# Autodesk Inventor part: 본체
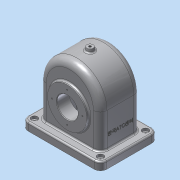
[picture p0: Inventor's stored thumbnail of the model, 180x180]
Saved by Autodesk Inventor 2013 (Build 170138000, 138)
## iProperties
Created: 2016-10
Part Number: 본체
Material: 알루미늄 6061
Document SubType Name: Modeling
Designer: Administrator
Mass: 1165.05 g
Surface Area: 1200.05 cm^2
Volume: 429.908 cm^3
Density: 2.71 g/cm^3
Author: Administrator
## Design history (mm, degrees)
sketch "스케치1"
  geometry: L1 (-43, 75)-(43, 75); L2 (55, 63)-(55, -63); L3 (43, -75)-(-43, -75); L4 (-55, -63)-(-55, 63); A1 r 12 centre (-43, 63) between (-43, 75) and (-55, 63); A2 r 12 centre (43, 63) between (55, 63) and (43, 75); A3 r 12 centre (43, -63) between (43, -75) and (55, -63); A4 r 12 centre (-43, -63) between (-55, -63) and (-43, -75); 6 further points
  constraints: 8 end point, 8 point on circle, 8 tangent, 6 point on line, 4 centre point, 3 equal radius, 2 midpoint, 2 parallel, 1 horizontal, 1 horizontal alignment, 1 perpendicular, 1 vertical alignment
  dimensions: "d0" = 110 distance of point (-55, 75) point (55, 75); "d2" = 150 distance of point (55, 75) point (55, -75); "d3" = 12 radius of A1
extrude "돌출1" new body sketch "스케치1" distance "d4" = 15; taper "d5" = 0 deg
sketch "스케치2"
  geometry: L1 (63, 15)-(-63, 15) reference; L2 (-63, 15)-(-75, 15) reference; L3 (75, 15)-(63, 15) reference; L4 (-58, 15)-(-58, 80); L5 (58, 80)-(58, 15); A1 r 58 centre (0, 80) between (58, 80) and (-58, 80); 1 further point
  constraints: 4 end point, 2 perpendicular, 2 point on circle, 2 point on line, 2 tangent, 1 centre point, 1 vertical alignment
  dimensions: "d6" = 80 distance of point (0, 0) A1.centre; "d7" = 58 radius of A1
extrude "돌출2" join sketch "스케치2" stored distance "d8" = 77; taper "d9" = 0 deg
sketch "스케치3"
  geometry: L1 (58, 80)-(58, 15) reference; L2 (-58, 15)-(-58, 80) reference; L3 (-63, 0)-(63, 0) reference; L4 (-52, 0)-(-52, 80); L5 (52, 80)-(52, 0); A1 r 58 centre (0, 80) between (58, 80) and (-58, 80) reference; A2 r 52 centre (0, 80) between (52, 80) and (-52, 80); 1 further point
  constraints: 4 end point, 2 point on circle, 2 point on line, 1 centre point
  dimensions: "d10" = 6 distance between parallel lines of L1 L5; "d11" = 6 distance between parallel lines of L2 L4; "d12" = 6 radial gap between concentric circles of A1 A2
extrude "돌출3" cut sketch "스케치3" stored distance "d13" = 67; taper "d14" = 0 deg
sketch "스케치4"
  geometry: L1 (0, 63)-(0, -63) reference; C1 r 31 at (-65, 0); 2 further points
  constraints: 1 centre point, 1 horizontal alignment, 1 midpoint
  dimensions: "d15" = 62 diameter of C1; "d17" = 65 distance from line of L1 C1.centre
extrude "돌출4" join sketch "스케치4" distance "d18" = 10; taper "d19" = 0 deg
sketch "스케치5"
  geometry: C1 r 37.5 at (65, 0); 1 further point
  constraints: 1 centre point, 1 horizontal alignment
  dimensions: "d20" = 75 diameter of C1; "d22" = 65 distance of C1.centre point (0, 0)
extrude "돌출5" join sketch "스케치5" distance "d23" = 5; taper "d24" = 0 deg
node "작업 평면1"
sketch "스케치6"
  geometry: C1 r 6 at (0, 0); 1 further point
  constraints: 1 centre point, 1 coincident
  dimensions: "d26" = 12 diameter of C1
extrude "돌출6" join sketch "스케치6" distance "d28" = 10; taper "d29" = 10 deg
sketch "스케치7"
  geometry: L1 (43.5, 27.5)-(43.5, 102.5) reference; L2 (33.5, 80)-(33.5, 132) reference; L3 (33.5, 0)-(33.5, 80) reference; L4 (43.5, 65)-(19.5, 65); L5 (19.5, 65)-(19.5, 93); L6 (19.5, 93)-(33.5, 104.747); L7 (33.5, 104.747)-(33.5, 65); 1 further point
  constraints: 8 end point, 3 point on line, 2 perpendicular, 1 midpoint
  dimensions: "d30" = 56 diameter of L5.end L4; "d32" = 50 deg angle of L6 L5; "d34" = 24 distance between parallel lines of L5 L1
revolve "회전1" sketch "스케치7" stored, may be unused: angle "d35" = 90 deg
hole "구멍1" diameter "d38" = 40; stored, may be unused: countersink angle "d42" = 90 deg, drill point angle "d44" = 118 deg; dims "d36" = 10, "d37" = 10, "d39" = 6, "d40" = 4, "d41" = 2, "d43" = 8
hole "구멍2" diameter "d47" = 4.459; stored, may be unused: countersink angle "d51" = 90 deg, drill point angle "d53" = 118 deg; dims "d48" = 20, "d49" = 4, "d50" = 2, "d52" = 8, "d124" = 10, "d125" = 10
hole "구멍3" diameter "d56" = 5; stored, may be unused: countersink angle "d60" = 90 deg, drill point angle "d62" = 118 deg; dims "d54" = 10, "d55" = 10, "d57" = 6, "d58" = 12, "d59" = 5, "d61" = 8
hole "구멍4" diameter "d65" = 5; stored, may be unused: countersink angle "d69" = 90 deg, drill point angle "d71" = 118 deg; dims "d63" = 10, "d64" = 10, "d66" = 6, "d67" = 12, "d68" = 5, "d70" = 8
hole "구멍5" diameter "d74" = 5; stored, may be unused: countersink angle "d78" = 90 deg, drill point angle "d80" = 118 deg; dims "d72" = 10, "d73" = 10, "d75" = 6, "d76" = 12, "d77" = 5, "d79" = 8
hole "구멍6" diameter "d83" = 5; stored, may be unused: countersink angle "d87" = 90 deg, drill point angle "d89" = 118 deg; dims "d81" = 10, "d82" = 10, "d84" = 6, "d85" = 12, "d86" = 5, "d88" = 8
sketch "스케치8"
  geometry: C1 r 20 at (0, 0) reference; 2 further points
  constraints: 1 horizontal alignment
  dimensions: "d90" = 26 distance of point (26, 0) C1.centre
hole "구멍7" sketch "스케치8" at (26, 0) diameter "d91" = 2.459; stored, may be unused: countersink angle "d95" = 90 deg, drill point angle "d97" = 118 deg; dims "d92" = 6, "d93" = 12, "d94" = 5, "d96" = 8
sketch "스케치9"
  geometry: C1 r 20 at (0, 0) reference; 2 further points
  constraints: 1 horizontal alignment
  dimensions: "d101" = 29 distance of C1.centre point (-29, 0)
hole "구멍8" sketch "스케치9" at (-29, 0) diameter "d102" = 2.459; stored, may be unused: countersink angle "d106" = 90 deg, drill point angle "d108" = 118 deg; dims "d103" = 6, "d104" = 12, "d105" = 5, "d107" = 8
sketch "스케치10"
  geometry: 2 further points
  constraints: 1 vertical alignment, 1 other
  dimensions: "d112" = 40 distance of point (38.5, -15) point (38.5, 25)
feature "엠보싱1" sketch "스케치10" dims "d0" = 110, "d2" = 150, "d3" = 12, "d6" = 80, "d7" = 58, "d113" = 0.5, "d114" = 0
fillet "모깎기1" dims "d115" = 13
fillet "모깎기2" dims "d116" = 8
fillet "모깎기3" dims "d117" = 3
fillet "모깎기4" dims "d118" = 3
fillet "모깎기5" dims "d119" = 3
fillet "모깎기6" dims "d120" = 3
chamfer "모따기1" distance "d121" = 1; stored, may be unused: second distance "d122" = 2, angle "d123" = 45 deg
node "솔리드1"
pattern_circular "원형 패턴1" dims angle "d99" = 360 deg
pattern_circular "원형 패턴2" dims angle "d110" = 360 deg
other parameters: "d25" = 144
